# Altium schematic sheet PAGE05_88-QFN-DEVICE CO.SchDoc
size 401 x 330 mm
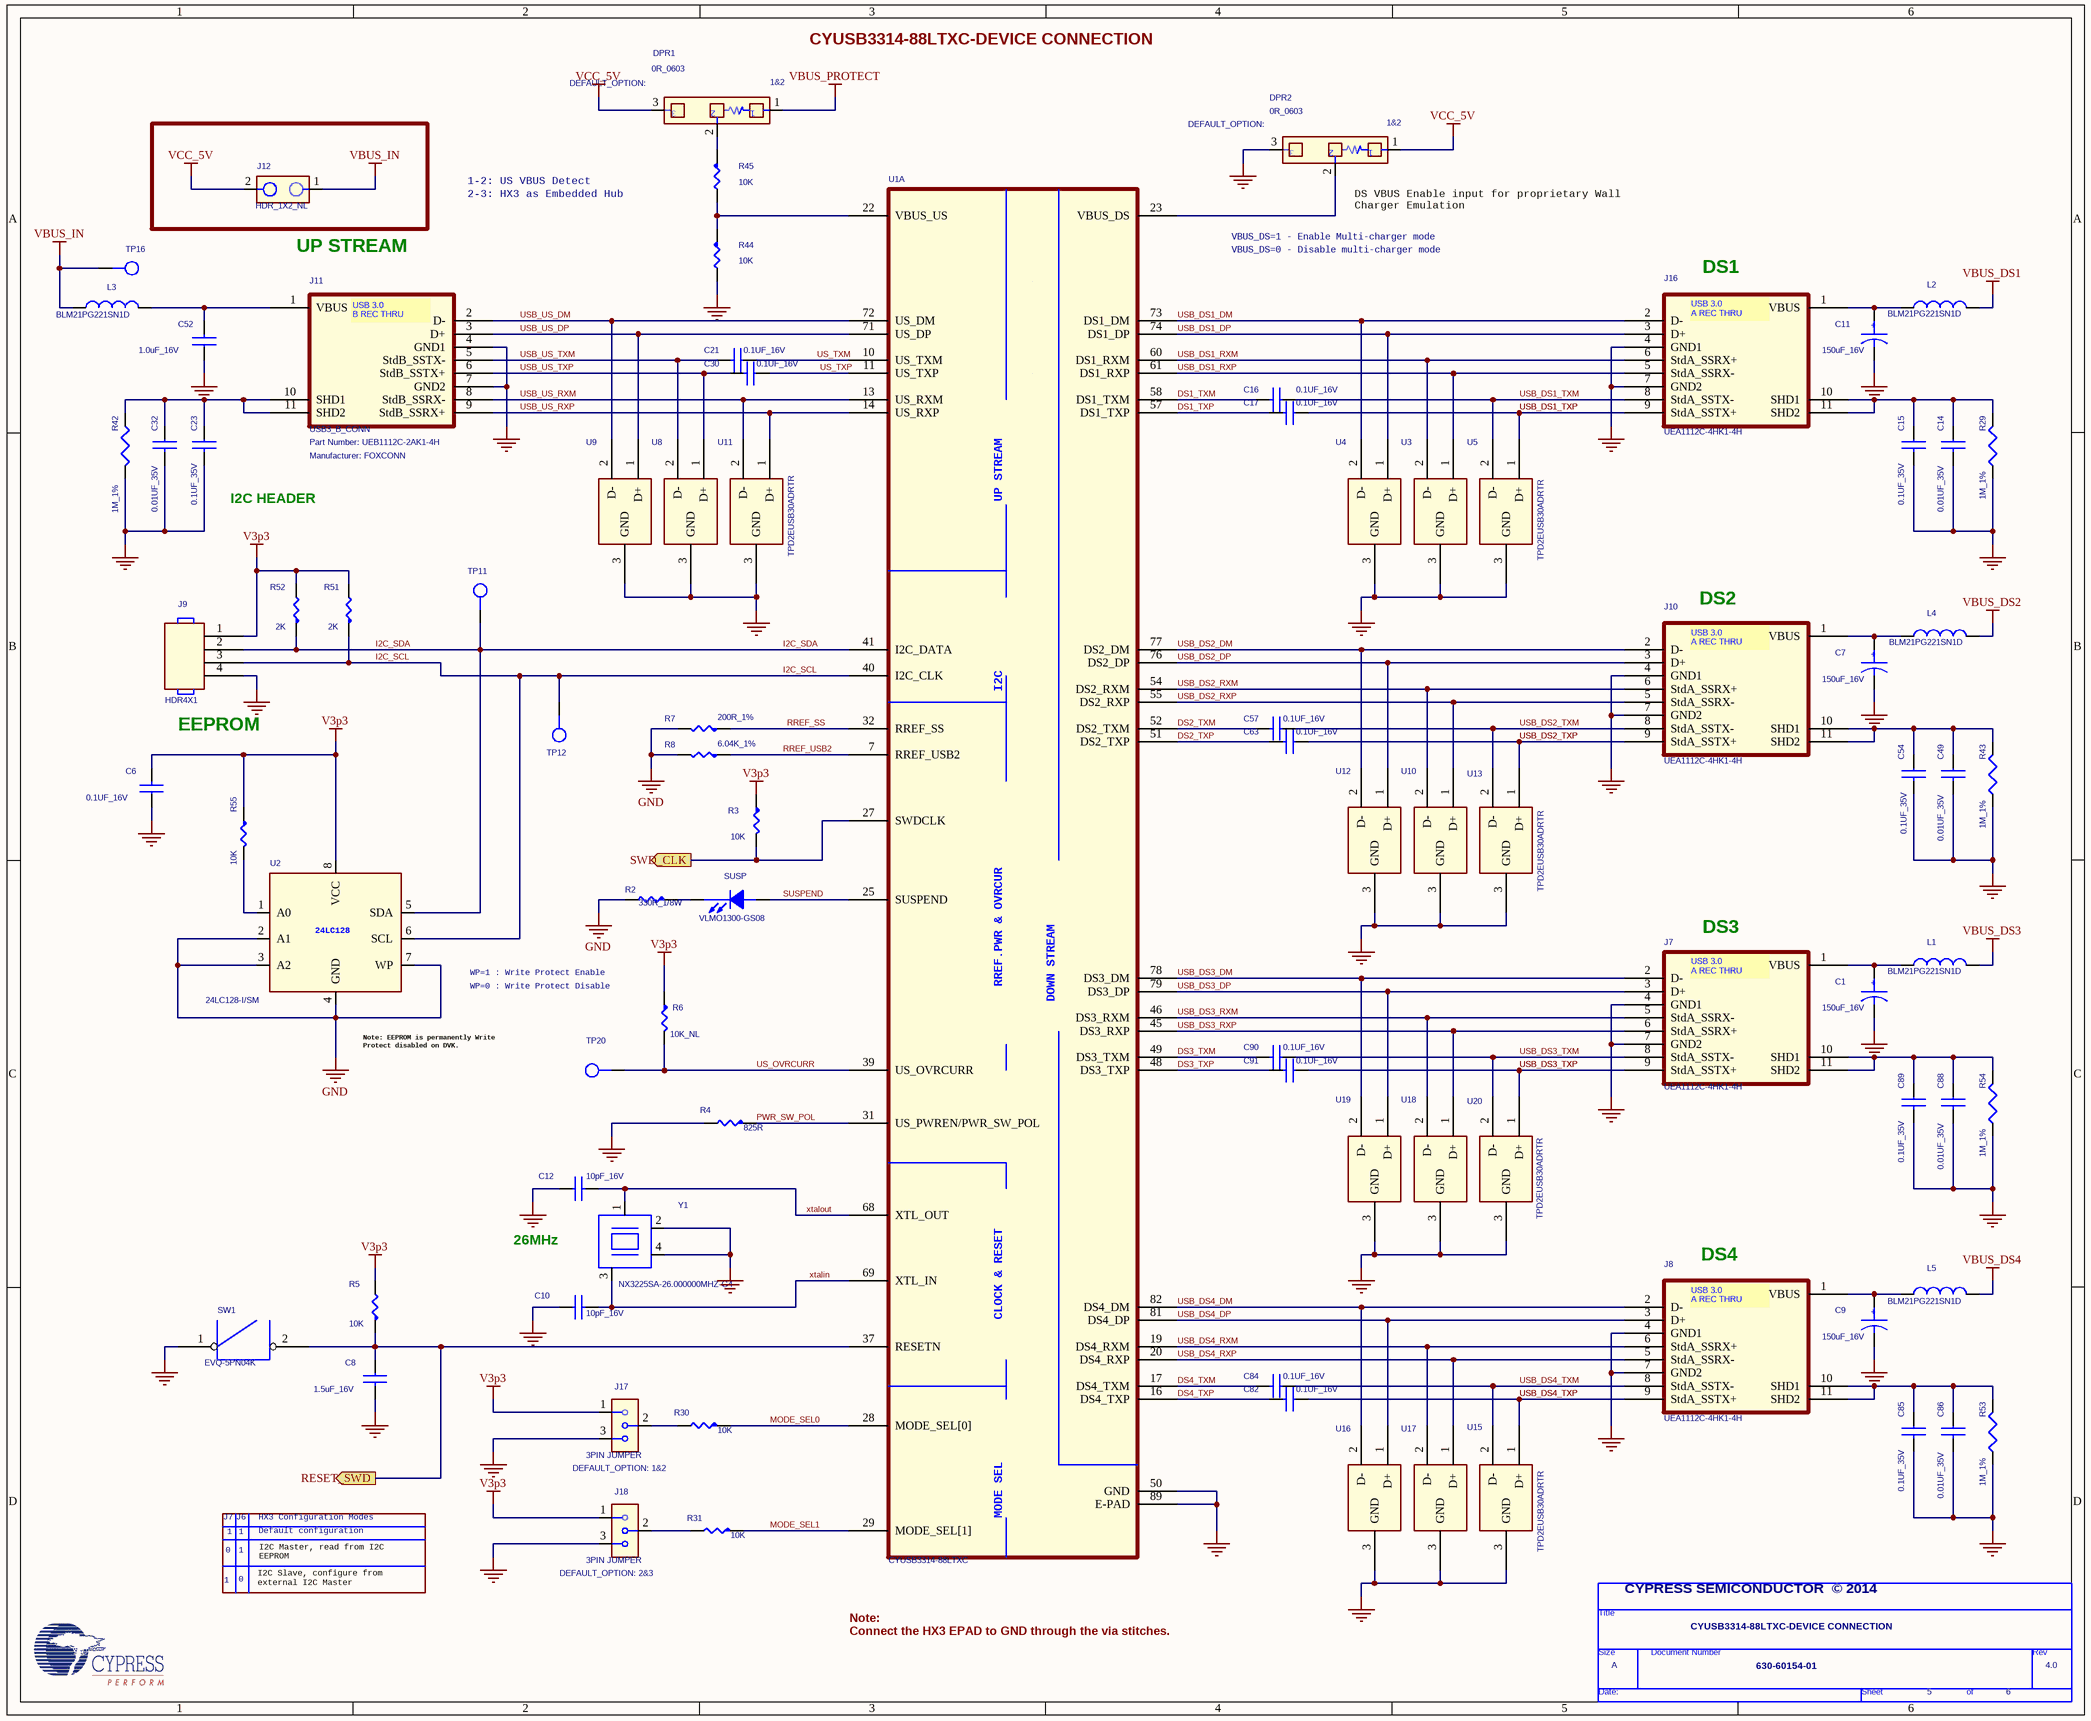
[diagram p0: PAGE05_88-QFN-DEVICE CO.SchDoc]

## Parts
*  Page Count: 6  Page Number: 5  Page Size: A  Title: CYUSB3314-88LTXC-DEVICE CONNECTION  RevCode: 4.0  Doc: 630-60154-01  (hidden comment: TitleBlock0)  (graphical)
C1  150uF_16V  [CAPAE660X800M]
C6  0.1UF_16V  [CAPC1005X56M]
C7  150uF_16V  [CAPAE660X800M]
C8  1.5uF_16V  [CAPC1608X90M]
C9  150uF_16V  [CAPAE660X800M]
C10  10pF_16V  [CAPC1608X90M]
C11  150uF_16V  [CAPAE660X800M]
C12  10pF_16V  [CAPC1608X90M]
C14  0.01UF_35V  [CAPC1005X55M]
C15  0.1UF_35V  [CAPC1005X55M]
C16  0.1UF_16V  [CAPC1005X56M]
C17  0.1UF_16V  [CAPC1005X56M]
C21  0.1UF_16V  [CAPC1005X56M]
C23  0.1UF_35V  [CAPC1005X55M]
C30  0.1UF_16V  [CAPC1005X56M]
C32  0.01UF_35V  [CAPC1005X55M]
C49  0.01UF_35V  [CAPC1005X55M]
C52  1.0uF_16V  [CAPC1005X56M]
C54  0.1UF_35V  [CAPC1005X55M]
C57  0.1UF_16V  [CAPC1005X56M]
C63  0.1UF_16V  [CAPC1005X56M]
C82  0.1UF_16V  [CAPC1005X56M]
C84  0.1UF_16V  [CAPC1005X56M]
C85  0.1UF_35V  [CAPC1005X55M]
C86  0.01UF_35V  [CAPC1005X55M]
C88  0.01UF_35V  [CAPC1005X55M]
C89  0.1UF_35V  [CAPC1005X55M]
C90  0.1UF_16V  [CAPC1005X56M]
C91  0.1UF_16V  [CAPC1005X56M]
DPR1  0R_0603  Mounting Status: 1&2  [RC0603_3P]
DPR2  0R_0603  Mounting Status: 1&2  [RC0603_3P]
J7  UEA1112C-4HK1-4H  [FOXCONN_UEA1112C-4HK1-4H]
J8  UEA1112C-4HK1-4H  [FOXCONN_UEA1112C-4HK1-4H]
J9  HDR4X1  [SAMTEC_TSW-104-08-G-S]
J10  UEA1112C-4HK1-4H  [FOXCONN_UEA1112C-4HK1-4H]
J11  USB3_B_CONN  Manufacturer: FOXCONN  [FOXCONN_UEB1112C-2AK1-4H]
J12  HDR_1X2_NL  [SAMTEC_TSW-102-08-G-S]
J16  UEA1112C-4HK1-4H  [FOXCONN_UEA1112C-4HK1-4H]
J17  3PIN JUMPER  DEFAULT_OPTION: 1&2  [TE_3-644456-3]
J18  3PIN JUMPER  DEFAULT_OPTION: 2&3  [TE_3-644456-3]
L1  BLM21PG221SN1D  [INDC2012X105M]
L2  BLM21PG221SN1D  [INDC2012X105M]
L3  BLM21PG221SN1D  [INDC2012X105M]
L4  BLM21PG221SN1D  [INDC2012X105M]
L5  BLM21PG221SN1D  [INDC2012X105M]
R2  330R_1/8W  [RESC1608X50M]
R3  10K  [RESC1005X40M]
R4  825R  [RESC1005X40M]
R5  10K  [RESC1608X55M]
R6  10K_NL  [RESC1005X40M]
R7  200R_1%  [RESC1608X50M]
R8  6.04K_1%  [RESC1608X55M_A]
R29  1M_1%  [RESC1608X55M]
R30  10K  [RESC1005X40M]
R31  10K  [RESC1005X40M]
R42  1M_1%  [RESC1608X55M]
R43  1M_1%  [RESC1608X55M]
R44  10K  [RESC1005X40M]
R45  10K  [RESC1005X40M]
R51  2K  [RESC1608X55M]
R52  2K  [RESC1608X55M]
R53  1M_1%  [RESC1608X55M]
R54  1M_1%  [RESC1608X55M]
R55  10K  [RESC1608X55M]
SUSP  VLMO1300-GS08  [LEDC1608X80M]
SW1  EVQ-5PN04K  [SW_EVQ-5PN04K]
TP11  TP_YEL  [KEYSTONE_5000]  (value not drawn)
TP12  TP_YEL  [KEYSTONE_5000]  (value not drawn)
TP16  TP_RED  [KEYSTONE_5000]  (value not drawn)
TP20  TP_YEL  [KEYSTONE_5000]  (value not drawn)
U1  CYUSB3314-88LTXC  [QFN40P1000X1000X100-89M]  (part A of 3)
U2  24LC128-I/SM  [SOIC127P790X203-8M]
U3  TPD2EUSB30ADRTR  [SOTFL35P100X50-3M]  (value not drawn)
U4  TPD2EUSB30ADRTR  [SOTFL35P100X50-3M]  (value not drawn)
U5  TPD2EUSB30ADRTR  [SOTFL35P100X50-3M]
U8  TPD2EUSB30ADRTR  [SOTFL35P100X50-3M]  (value not drawn)
U9  TPD2EUSB30ADRTR  [SOTFL35P100X50-3M]  (value not drawn)
U10  TPD2EUSB30ADRTR  [SOTFL35P100X50-3M]  (value not drawn)
U11  TPD2EUSB30ADRTR  [SOTFL35P100X50-3M]
U12  TPD2EUSB30ADRTR  [SOTFL35P100X50-3M]  (value not drawn)
U13  TPD2EUSB30ADRTR  [SOTFL35P100X50-3M]
U15  TPD2EUSB30ADRTR  [SOTFL35P100X50-3M]
U16  TPD2EUSB30ADRTR  [SOTFL35P100X50-3M]  (value not drawn)
U17  TPD2EUSB30ADRTR  [SOTFL35P100X50-3M]  (value not drawn)
U18  TPD2EUSB30ADRTR  [SOTFL35P100X50-3M]  (value not drawn)
U19  TPD2EUSB30ADRTR  [SOTFL35P100X50-3M]  (value not drawn)
U20  TPD2EUSB30ADRTR  [SOTFL35P100X50-3M]
Y1  NX3225SA-26.000000MHZ-G4  [OSCCC250X320X70-4M]

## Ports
RESET_SWD (out), SWD_CLK (out)

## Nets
GND: C1.2 C6.1 C7.2 C8.2 C9.2 C10.1 C11.2 C12.1 C14.2 C15.2 C23.2 C32.2 C49.2 C52.1 C54.2 C85.2 C86.2 C88.2 C89.2 DPR2.3 J7.4(GND1) J7.7(GND2) J8.4(GND1) J8.7(GND2) J9.4 J10.4(GND1) J10.7(GND2) J11.4(GND1) J11.7(GND2) J16.4(GND1) J16.7(GND2) J17.3 J18.3 R2.2 R4.2 R7.2 R8.2 R29.2 R42.2 R43.2 R44.2 R53.2 R54.2 SW1.1 U1.50(GND) U1.89(E-PAD) U2.2(A1) U2.3(A2) U2.4(GND) U2.7(WP) U3.3(GND) U4.3(GND) U5.3(GND) U8.3(GND) U9.3(GND) U10.3(GND) U11.3(GND) U12.3(GND) U13.3(GND) U15.3(GND) U16.3(GND) U17.3(GND) U18.3(GND) U19.3(GND) U20.3(GND) Y1.2 Y1.4
V3p3: C6.2 J9.1 J17.1 J18.1 R3.1 R5.2 R6.1 R51.2 R52.2 R55.1 U2.8(VCC)
VBUS_DS1: L2.1
VBUS_DS2: L4.1
VBUS_DS3: L1.1
VBUS_DS4: L5.1
VBUS_IN: J12.1 L3.1 TP16.1(TP)
VBUS_PROTECT: DPR1.1
VCC_5V: DPR1.3 DPR2.1 J12.2
DS1_TXM: C16.2 U1.58(DS1_TXM)
DS1_TXP: C17.2 U1.57(DS1_TXP)
DS2_TXM: C57.2 U1.52(DS2_TXM)
DS2_TXP: C63.2 U1.51(DS2_TXP)
DS3_TXM: C90.2 U1.49(DS3_TXM)
DS3_TXP: C91.2 U1.48(DS3_TXP)
DS4_TXM: C84.2 U1.17(DS4_TXM)
DS4_TXP: C82.2 U1.16(DS4_TXP)
I2C_SCL: J9.3 R51.1 TP12.1(TP) U1.40(I2C_CLK) U2.6(SCL)
I2C_SDA: J9.2 R52.1 TP11.1(TP) U1.41(I2C_DATA) U2.5(SDA)
MODE_SEL0: R30.1 U1.28(MODE_SEL[0])
MODE_SEL1: R31.1 U1.29(MODE_SEL[1])
PWR_SW_POL: R4.1 U1.31(US_PWREN/PWR_SW_POL)
RESET_SWD: C8.1 R5.1 SW1.2 U1.37(RESETN) ; port RESET_SWD
RREF_SS: R7.1 U1.32(RREF_SS)
RREF_USB2: R8.1 U1.7(RREF_USB2)
SUSPEND: SUSP.1(ANODE) U1.25(SUSPEND)
SWD_CLK: R3.2 U1.27(SWDCLK) ; port SWD_CLK
US_OVRCURR: R6.2 TP20.1(TP) U1.39(US_OVRCURR)
US_TXM: C21.1 U1.10(US_TXM)
US_TXP: C30.1 U1.11(US_TXP)
USB_DS1_DM: J16.2(D-) U1.73(DS1_DM) U4.2(D-)
USB_DS1_DP: J16.3(D+) U1.74(DS1_DP) U4.1(D+)
USB_DS1_RXM: J16.6(StdA_SSRX+) U1.60(DS1_RXM) U3.2(D-)
USB_DS1_RXP: J16.5(StdA_SSRX-) U1.61(DS1_RXP) U3.1(D+)
USB_DS1_TXM: C16.1 J16.8(StdA_SSTX-) U5.2(D-)
USB_DS1_TXP: C17.1 J16.9(StdA_SSTX+) U5.1(D+)
USB_DS2_DM: J10.2(D-) U1.77(DS2_DM) U12.2(D-)
USB_DS2_DP: J10.3(D+) U1.76(DS2_DP) U12.1(D+)
USB_DS2_RXM: J10.6(StdA_SSRX+) U1.54(DS2_RXM) U10.2(D-)
USB_DS2_RXP: J10.5(StdA_SSRX-) U1.55(DS2_RXP) U10.1(D+)
USB_DS2_TXM: C57.1 J10.8(StdA_SSTX-) U13.2(D-)
USB_DS2_TXP: C63.1 J10.9(StdA_SSTX+) U13.1(D+)
USB_DS3_DM: J7.2(D-) U1.78(DS3_DM) U19.2(D-)
USB_DS3_DP: J7.3(D+) U1.79(DS3_DP) U19.1(D+)
USB_DS3_RXM: J7.5(StdA_SSRX-) U1.46(DS3_RXM) U18.2(D-)
USB_DS3_RXP: J7.6(StdA_SSRX+) U1.45(DS3_RXP) U18.1(D+)
USB_DS3_TXM: C90.1 J7.8(StdA_SSTX-) U20.2(D-)
USB_DS3_TXP: C91.1 J7.9(StdA_SSTX+) U20.1(D+)
USB_DS4_DM: J8.2(D-) U1.82(DS4_DM) U16.2(D-)
USB_DS4_DP: J8.3(D+) U1.81(DS4_DP) U16.1(D+)
USB_DS4_RXM: J8.6(StdA_SSRX+) U1.19(DS4_RXM) U17.2(D-)
USB_DS4_RXP: J8.5(StdA_SSRX-) U1.20(DS4_RXP) U17.1(D+)
USB_DS4_TXM: C84.1 J8.8(StdA_SSTX-) U15.2(D-)
USB_DS4_TXP: C82.1 J8.9(StdA_SSTX+) U15.1(D+)
USB_US_DM: J11.2(D-) U1.72(US_DM) U9.2(D-)
USB_US_DP: J11.3(D+) U1.71(US_DP) U9.1(D+)
USB_US_RXM: J11.8(StdB_SSRX-) U1.13(US_RXM) U11.2(D-)
USB_US_RXP: J11.9(StdB_SSRX+) U1.14(US_RXP) U11.1(D+)
USB_US_TXM: C21.2 J11.5(StdB_SSTX-) U8.2(D-)
USB_US_TXP: C30.2 J11.6(StdB_SSTX+) U8.1(D+)
xtalin: C10.2 U1.69(XTL_IN) Y1.3
xtalout: C12.2 U1.68(XTL_OUT) Y1.1
NetC1_1: C1.1 J7.1(VBUS) L1.2
NetC7_1: C7.1 J10.1(VBUS) L4.2
NetC9_1: C9.1 J8.1(VBUS) L5.2
NetC11_1: C11.1 J16.1(VBUS) L2.2
NetC14_1: C14.1 C15.1 J16.10(SHD1) J16.11(SHD2) R29.1
NetC23_1: C23.1 C32.1 J11.10(SHD1) J11.11(SHD2) R42.1
NetC49_1: C49.1 C54.1 J10.10(SHD1) J10.11(SHD2) R43.1
NetC52_2: C52.2 J11.1(VBUS) L3.2
NetC85_1: C85.1 C86.1 J8.10(SHD1) J8.11(SHD2) R53.1
NetC88_1: C88.1 C89.1 J7.10(SHD1) J7.11(SHD2) R54.1
NetDPR1_2: DPR1.2 R45.1
NetDPR2_2: DPR2.2 U1.23(VBUS_DS)
NetJ17_2: J17.2 R30.2
NetJ18_2: J18.2 R31.2
NetR2_1: R2.1 SUSP.2(CATHODE)
NetR44_1: R44.1 R45.2 U1.22(VBUS_US)
NetR55_2: R55.2 U2.1(A0)

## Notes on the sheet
- CYUSB3314-88LTXC-DEVICE CONNECTION
- 1-2: US VBUS Detect
- 2-3: HX3 as Embedded Hub
- (near DPR2) DS VBUS Enable input for proprietary Wall
  Charger Emulation
- UP STREAM
- VBUS_DS=0 - Disable multi-charger mode
- VBUS_DS=1 - Enable Multi-charger mode
- (near J16) DS1
- (near C23) I2C HEADER
- (near J10) DS2
- EEPROM
- (near J7) DS3
- WP=1 : Write Protect Enable
- WP=0 : Write Protect Disable
- Note: EEPROM is permanently Write
  Protect disabled on DVK.
- 26MHz
- (near J8) DS4
- J7
- 1
- J6
- HX3 Configuration Modes
- Default configuration
- 0
- I2C Slave, configure from
  external I2C Master
- I2C Master, read from I2C
  EEPROM
- (near *) CYPRESS SEMICONDUCTOR  © 2014
- Note:
  Connect the HX3 EPAD to GND through the via stitches.

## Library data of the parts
C1 C7 C9 C11 = CAP POL: CAP ALUM 150UF 16V 20% SMD; Part Number: EEE-FK1C151XP; Manufacturer: Panasonic Electronic Components
C6 C10 C12 C16 C17 C21 C30 C52 C57 C63 C82 C84 C90 C91 = CAPACITOR NON-POL
C8 = CAPACITOR NON-POL: CAP CER 1.5UF 10V 10% X7R 0805; Manufacturer: TDK Corporation
C14 C32 C49 C86 C88 = CAPACITOR NON-POL: Part Number: C1005X7R1V103M050BB
C15 C23 C54 C85 C89 = CAPACITOR NON-POL: Part Number: C1005X7R1V104K050BB
DPR1 DPR2 = DPR12_0: Resistor, 4.7K, 0402, 1/10W, 5%; Part Number: ERJ-2GEJ472X
J7 = UEA1112C-4HK1-4H: 9 Position Right Angle 3.0 USB Connector; Manufacturer: FOXCONN
J8 J10 J16 = UEA1112C_TX: 9 Position Right Angle 3.0 USB Connector; Manufacturer: FOXCONN
J9 = HEADER 4: CONN HEADER 4POS .100" SNGL GOLD; Manufacturer: Samtec Inc; Part Number: TSW-104-08-G-S
J11 = UEB1112C-2AK1-4H: USB 3.0 B Series Right Angle,T/H 9 Pos
J12 = HEADER_1x2: Manufacturer: Samtec Inc; Part Number: TSW-102-08-G-S
J17 J18 = 3PIN JUM: CONN HEADER VERT 3POS .100 TIN; Part Number: 3-644456-3; Manufacturer: Tyco Electronics
L1 L2 L4 L5 = INDUCTOR: FERRITE CHIP 220 OHM 2A 0805; Manufacturer: Murata; DEVICE: L3
L3 = INDUCTOR: FERRITE CHIP 220 OHM 2A 0805; Manufacturer: Murata
R2 = R_Dup1
R3 = R_Dup1: RES 10.0K OHM 1/10W 1% 0603 SMD; Manufacturer: Panasonic - ECG; Part Number: ERJ-3EKF1002V
R4 R30 R31 = R_Dup1: Manufacturer: Panasonic; Part Number: ERJ-2RKF49.9X
R5 = R_Dup1: Part Number: ERJ-2RKF49.9X; Manufacturer: Panasonic
R6 R55 = R_Dup1: RES 10.0K OHM 1/10W 1% 0603 SMD; Part Number: ERJ-3EKF1002V; Manufacturer: Panasonic - ECG
R7 = R_Dup1: RES 200 OHM 1% 0603 SMD; Manufacturer: Stackpole; Part Number: RNCP0603FTD200R
R8 = R_Dup1: RES 6.04K OHM .25W 1% 0603 SMD; Part Number: CRCW06036K04FKEAHP; Manufacturer: Vishay Dale
R29 = R: RES 1M OHM 1/10W 1% 0603 SMD; Manufaturer: Panasonic; Part Number: ERJ-3EKF1004V
R42 = R: RES 1M OHM 1/10W 1% 0603 SMD; Part Number: ERJ-3EKF1004V; Manufacturer: Panasonic
R43 = R: RES 1M OHM 1/10W 1% 0603 SMD; Manufacturer: Panasonic; PART_NUMBER: ERJ-3EKF1004V
R44 = R_Dup1: Part Number: ERJ-2RKF4990X; Manufacturer: Panasonic
R45 = R_Dup1: Manufacturer: Panasonic; Part Number: ERJ-2GE0R00X
R51 = R_Dup1: RES 2.00K OHM 1/10W 1% 0603 SMD; Part Number: MCR03EZPFX2001; Manufacturer: Rohm Semiconductor
R52 = R_Dup1: RES 2.00K OHM 1/10W 1% 0603 SMD; Manufacturer: Rohm Semiconductor; Part Number: MCR03EZPFX2001
R53 R54 = R: RES 1M OHM 1/10W 1% 0603 SMD; Manufacturer: Panasonic; Part Number: ERJ-3EKF1004V
SUSP = LED
SW1 = B3U1000P
TP11 TP20 = TP: TEST POINT PC MINI .040"D RED; PART_NUMBER: 5000; Manufacturer: Keystone
TP12 TP16 = TP: TEST POINT PC MINI .040"D RED; Part Number: 5000; Manufacturer: Keystone
U1 = CYUSB3314-88LTXC_2
U2 = 24LC128: IC EEPROM 128KBIT 400KHZ 8SOIC; Manufacturer: Microchip Technology
Y1 = CRYSTAL_1: Manufacturer: NDK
